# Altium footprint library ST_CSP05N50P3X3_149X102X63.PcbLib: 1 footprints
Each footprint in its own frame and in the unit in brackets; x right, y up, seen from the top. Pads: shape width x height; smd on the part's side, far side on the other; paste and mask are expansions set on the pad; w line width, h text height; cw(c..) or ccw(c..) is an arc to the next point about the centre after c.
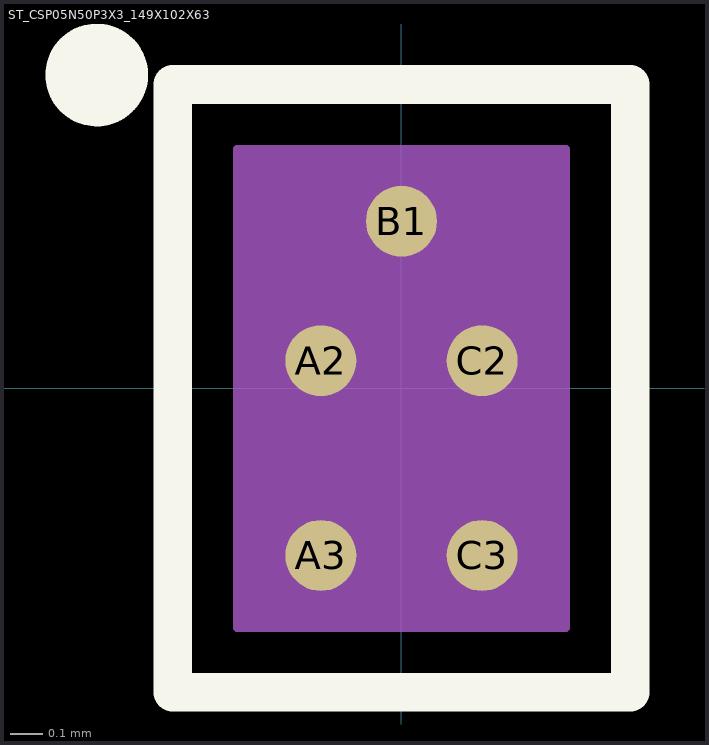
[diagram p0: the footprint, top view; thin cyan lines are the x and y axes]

## ST_CSP05N50P3X3_149X102X63 [mm] "ST_CSP05N50P3X3_149X102X63"
pads (5):
  round 0.22 smd mask+0.05: A2(-0.25,0.086) A3(-0.25,-0.519) B1(0,0.519) C2(0.25,0.086) C3(0.25,-0.519)
Top Overlay:
  circle w0.2: c-0.945,0.972 r0.059
  lines w0.12: -0.71,-0.943 0.71,-0.943 0.71,0.943 -0.71,0.943 -0.71,-0.943
Top Paste:
  rectangle: -0.36,-0.024 -0.14,0.196
  rectangle: 0.14,-0.024 0.36,0.196
  rectangle: -0.11,0.409 0.11,0.629
  rectangle: -0.36,-0.629 -0.14,-0.409
  rectangle: 0.14,-0.629 0.36,-0.409
Mechanical 5:
  text "A2" at -0.66,0.082 h0.1
  text "B1" at -0.01,0.781 h0.1
  text "C2" at 0.54,0.082 h0.1
  text "C3" at 0.19,-0.868 h0.1
  text "A3" at -0.36,-0.868 h0.1
Mechanical 6:
  lines w0.025: -0.51,-0.743 -0.51,0.743 0.51,0.743 0.51,-0.743 -0.51,-0.743
Mechanical 7:
  region: -0.51,-0.743 -0.51,0.743 0.51,0.743 0.51,-0.743
3D body: height 0.63, standoff 0.26, extent -0.51,-0.743 0.51,0.743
